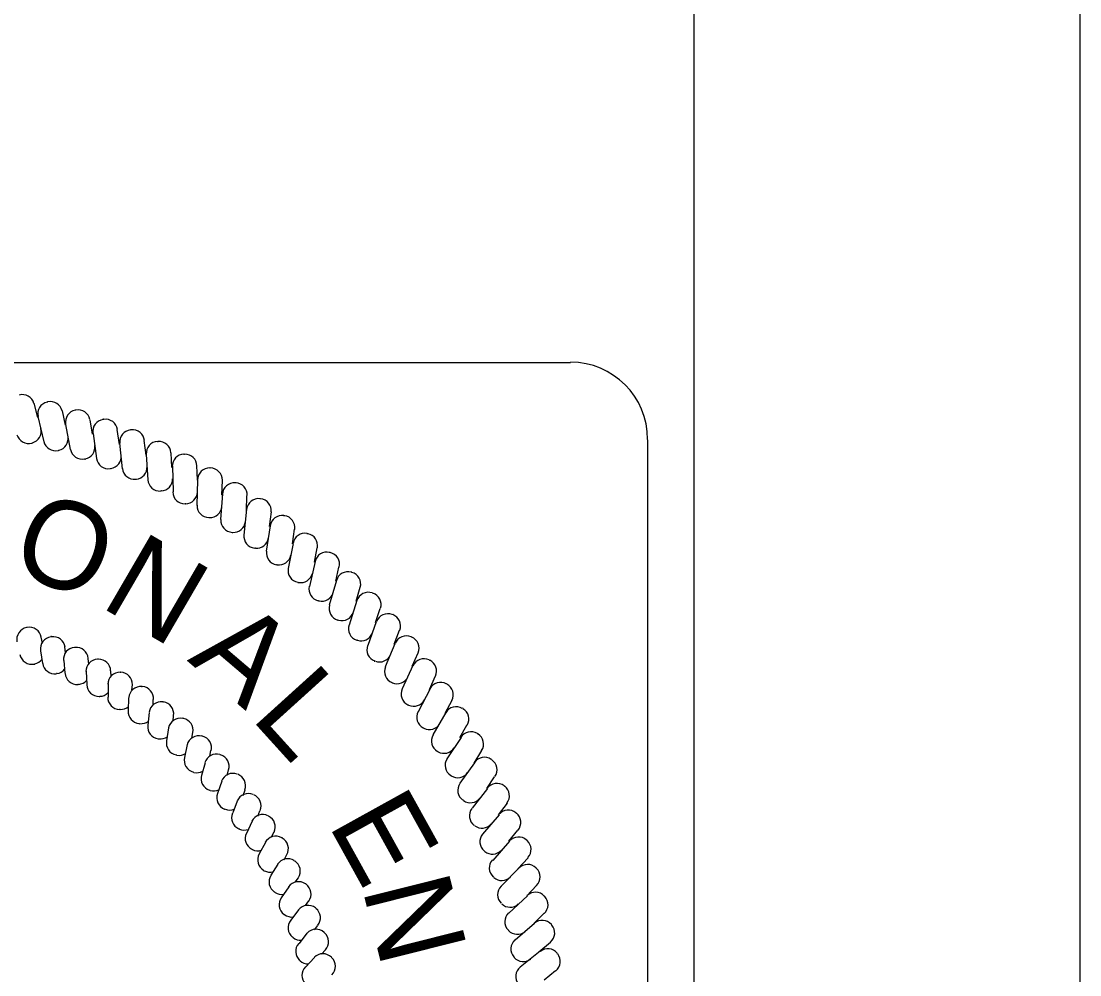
# Model space of a CAD drawing. Extents: x 1458004.1 to 1458040.9, y 194172.7 to 194198.1.
# Drawn here: x 1458038.688 to 1458040.06, y 194177.253 to 194178.489 of the extents above; entities that cross this region are included whole.
import ezdxf

# ---------------------------------------------------------------- set-up
doc = ezdxf.new("R2010")
doc.units = 0
for name, color, linetype in [('Border_9', 7, 'Continuous'), ('Eng_Stamp', 7, 'Continuous'), ('Eng_Stamp_Text_4', 7, 'Continuous'), ('IPlot_Plot_Limits', 7, 'Continuous'), ('Text_Box_4', 7, 'Continuous')]:
    doc.layers.add(name, color=color, linetype=linetype)

msp = doc.modelspace()

# ---------------------------------------------------------------- linework, layer by layer
at = {"layer": 'Border_9'}
msp.add_line((1458039.56, 194194.2392), (1458039.56, 194174.2392), dxfattribs=at)
at = {"layer": 'Eng_Stamp'}
for p, q in [((1458038.71, 194177.9758), (1458038.705, 194177.9942)), ((1458038.7225, 194177.9958), (1458038.7217, 194177.995)), ((1458038.71, 194177.9767), (1458038.7175, 194177.9442)), ((1458038.7458, 194177.9658), (1458038.7417, 194177.9842)), ((1458038.7592, 194177.985), (1458038.7583, 194177.985)), ((1458038.7458, 194177.9667), (1458038.7517, 194177.9342)), ((1458038.7808, 194177.9542), (1458038.7775, 194177.9725)), ((1458038.795, 194177.9733), (1458038.7942, 194177.9733)), ((1458038.7817, 194177.955), (1458038.7858, 194177.9225)), ((1458038.8158, 194177.9408), (1458038.8125, 194177.96)), ((1458038.8308, 194177.96), (1458038.83, 194177.9592)), ((1458038.7017, 194177.9425), (1458038.7025, 194177.9425)), ((1458038.8158, 194177.9425), (1458038.8192, 194177.9092)), ((1458038.85, 194177.9267), (1458038.8475, 194177.9458)), ((1458038.8658, 194177.9442), (1458038.865, 194177.9442)), ((1458038.7367, 194177.9325), (1458038.7375, 194177.9333)), ((1458038.7708, 194177.9217), (1458038.7717, 194177.9217)), ((1458038.85, 194177.9275), (1458038.8525, 194177.895)), ((1458038.8833, 194177.9108), (1458038.8825, 194177.93)), ((1458038.9, 194177.9275), (1458038.8992, 194177.9275)), ((1458038.8042, 194177.9092), (1458038.805, 194177.91)), ((1458038.8842, 194177.9125), (1458038.885, 194177.8792)), ((1458038.9167, 194177.8942), (1458038.9158, 194177.9133)), ((1458038.9333, 194177.91), (1458038.9325, 194177.91)), ((1458038.8367, 194177.8958), (1458038.8375, 194177.8958)), ((1458038.9167, 194177.895), (1458038.9158, 194177.8617)), ((1458038.9483, 194177.875), (1458038.9492, 194177.8942)), ((1458038.8692, 194177.8808), (1458038.87, 194177.8808)), ((1458038.9667, 194177.8908), (1458038.9658, 194177.8908)), ((1458038.9492, 194177.8767), (1458038.9467, 194177.8433)), ((1458038.98, 194177.855), (1458038.9808, 194177.8742)), ((1458038.9983, 194177.87), (1458038.9975, 194177.87)), ((1458038.9008, 194177.8642), (1458038.9017, 194177.8642)), ((1458038.98, 194177.8567), (1458038.9767, 194177.8233)), ((1458039.01, 194177.8342), (1458039.0125, 194177.8533)), ((1458038.9317, 194177.8458), (1458038.9325, 194177.8458)), ((1458039.03, 194177.8483), (1458039.0283, 194177.8483)), ((1458038.9617, 194177.8267), (1458038.9625, 194177.8267)), ((1458039.0108, 194177.835), (1458039.0058, 194177.8025)), ((1458039.04, 194177.8117), (1458039.0425, 194177.8308)), ((1458039.06, 194177.825), (1458039.0583, 194177.825)), ((1458039.0408, 194177.8125), (1458039.0342, 194177.78)), ((1458038.9908, 194177.8067), (1458038.9917, 194177.8067)), ((1458039.0683, 194177.7883), (1458039.0717, 194177.8067)), ((1458039.0883, 194177.8008), (1458039.0875, 194177.8008)), ((1458039.0192, 194177.785), (1458039.02, 194177.785)), ((1458039.0692, 194177.7892), (1458039.0617, 194177.7567)), ((1458039.0958, 194177.7633), (1458039.1, 194177.7817)), ((1458039.1167, 194177.775), (1458039.1158, 194177.775)), ((1458039.0467, 194177.7617), (1458039.0475, 194177.7617)), ((1458039.0967, 194177.7642), (1458039.0875, 194177.7325)), ((1458039.1225, 194177.7375), (1458039.1275, 194177.7558)), ((1458039.1442, 194177.7475), (1458039.1433, 194177.7483)), ((1458039.0733, 194177.7383), (1458039.0742, 194177.7383)), ((1458039.1233, 194177.7383), (1458039.1133, 194177.7067)), ((1458039.1475, 194177.71), (1458039.1533, 194177.7283)), ((1458039.1692, 194177.72), (1458039.1692, 194177.7208)), ((1458038.6958, 194177.7033), (1458038.695, 194177.7033)), ((1458039.0983, 194177.7133), (1458039.0992, 194177.7133)), ((1458039.1483, 194177.7108), (1458039.1375, 194177.68)), ((1458038.7158, 194177.6833), (1458038.7142, 194177.6908)), ((1458038.7275, 194177.6917), (1458038.7267, 194177.6917)), ((1458039.1717, 194177.6817), (1458039.1783, 194177.7)), ((1458039.1942, 194177.6908), (1458039.1933, 194177.6917)), ((1458038.7458, 194177.6708), (1458038.745, 194177.6783)), ((1458038.7583, 194177.6775), (1458038.7575, 194177.6775)), ((1458039.1233, 194177.6875), (1458039.1242, 194177.6867)), ((1458039.1725, 194177.6825), (1458039.16, 194177.6525)), ((1458038.7133, 194177.6733), (1458038.7158, 194177.6567)), ((1458038.7433, 194177.6608), (1458038.745, 194177.6442)), ((1458038.7758, 194177.6558), (1458038.775, 194177.6633)), ((1458038.7883, 194177.6625), (1458038.7875, 194177.6625)), ((1458039.195, 194177.6533), (1458039.2025, 194177.6708)), ((1458039.2175, 194177.6608), (1458039.2167, 194177.6608)), ((1458038.705, 194177.6558), (1458038.7058, 194177.6558)), ((1458038.7725, 194177.6467), (1458038.7733, 194177.6292)), ((1458038.805, 194177.64), (1458038.8042, 194177.6475)), ((1458039.1458, 194177.66), (1458039.1467, 194177.66)), ((1458039.1958, 194177.6542), (1458039.1817, 194177.6242)), ((1458038.7342, 194177.6442), (1458038.735, 194177.6442)), ((1458038.8175, 194177.645), (1458038.8167, 194177.645)), ((1458039.2175, 194177.6233), (1458039.225, 194177.6408)), ((1458038.7617, 194177.63), (1458038.7625, 194177.63)), ((1458038.8008, 194177.6308), (1458038.8008, 194177.6133)), ((1458038.8317, 194177.6225), (1458038.8325, 194177.6292)), ((1458038.845, 194177.6267), (1458038.8442, 194177.6267)), ((1458039.1683, 194177.6325), (1458039.1692, 194177.6317)), ((1458039.2183, 194177.6242), (1458039.2025, 194177.5942)), ((1458039.24, 194177.63), (1458039.2392, 194177.6308)), ((1458038.7892, 194177.6142), (1458038.79, 194177.6142)), ((1458038.8275, 194177.6125), (1458038.8267, 194177.5958)), ((1458038.8592, 194177.6025), (1458038.8592, 194177.61)), ((1458038.8725, 194177.6067), (1458038.8717, 194177.6067)), ((1458039.2375, 194177.5925), (1458039.2467, 194177.6092)), ((1458038.8158, 194177.5975), (1458038.8167, 194177.5975)), ((1458038.8542, 194177.5933), (1458038.8525, 194177.5767)), ((1458039.1892, 194177.6033), (1458039.19, 194177.6033)), ((1458039.2383, 194177.5933), (1458039.2217, 194177.5642)), ((1458039.2608, 194177.5983), (1458039.26, 194177.5992)), ((1458038.8408, 194177.5792), (1458038.8417, 194177.5792)), ((1458038.885, 194177.5825), (1458038.8858, 194177.5892)), ((1458038.8983, 194177.5858), (1458038.8975, 194177.5858)), ((1458038.8792, 194177.5733), (1458038.8767, 194177.5567)), ((1458038.9092, 194177.56), (1458038.9108, 194177.5675)), ((1458039.2092, 194177.5733), (1458039.21, 194177.5733)), ((1458039.2567, 194177.5608), (1458039.2658, 194177.5767)), ((1458039.28, 194177.5658), (1458039.2792, 194177.5658)), ((1458038.8658, 194177.5592), (1458038.8667, 194177.5592)), ((1458038.9033, 194177.5517), (1458038.9, 194177.535)), ((1458038.9233, 194177.5625), (1458038.9225, 194177.5633)), ((1458039.2583, 194177.5608), (1458039.24, 194177.5333)), ((1458038.8892, 194177.5383), (1458038.89, 194177.5383)), ((1458038.9325, 194177.5367), (1458038.9342, 194177.5442)), ((1458038.9467, 194177.5383), (1458038.9458, 194177.5383)), ((1458039.2275, 194177.5433), (1458039.2283, 194177.5425)), ((1458039.275, 194177.5275), (1458039.285, 194177.5442)), ((1458038.9267, 194177.5283), (1458038.9217, 194177.5117)), ((1458039.2758, 194177.5283), (1458039.2567, 194177.5017)), ((1458039.2983, 194177.5325), (1458039.2975, 194177.5325)), ((1458038.9117, 194177.5158), (1458038.9117, 194177.5158)), ((1458038.955, 194177.5117), (1458038.9567, 194177.5192)), ((1458038.9683, 194177.5133), (1458038.9683, 194177.5133)), ((1458039.245, 194177.5117), (1458039.2458, 194177.5117)), ((1458039.2917, 194177.495), (1458039.3017, 194177.51)), ((1458038.9483, 194177.5042), (1458038.9425, 194177.4883)), ((1458039.315, 194177.4975), (1458039.3142, 194177.4983)), ((1458038.9325, 194177.4925), (1458038.9333, 194177.4925)), ((1458038.9758, 194177.4858), (1458038.9783, 194177.4933)), ((1458038.9892, 194177.4867), (1458038.9892, 194177.4867)), ((1458039.2925, 194177.495), (1458039.2725, 194177.4692)), ((1458038.9517, 194177.4683), (1458038.9525, 194177.4675)), ((1458038.9683, 194177.4783), (1458038.9625, 194177.4633)), ((1458039.2608, 194177.48), (1458039.2617, 194177.4792)), ((1458039.3067, 194177.4608), (1458039.3183, 194177.4758)), ((1458038.995, 194177.4592), (1458038.9975, 194177.4658)), ((1458039.0092, 194177.4592), (1458039.0083, 194177.4592)), ((1458039.3075, 194177.4608), (1458039.2858, 194177.4358)), ((1458039.33, 194177.4625), (1458039.3292, 194177.4633)), ((1458038.9708, 194177.4425), (1458038.9717, 194177.4425)), ((1458038.9875, 194177.4525), (1458038.98, 194177.4367)), ((1458039.275, 194177.4475), (1458039.2758, 194177.4467)), ((1458039.0125, 194177.4317), (1458039.0158, 194177.4383)), ((1458039.0267, 194177.4308), (1458039.0258, 194177.4308)), ((1458039.32, 194177.4267), (1458039.3317, 194177.4408)), ((1458039.3442, 194177.4275), (1458039.3433, 194177.4275)), ((1458038.9875, 194177.4158), (1458038.9883, 194177.4158)), ((1458039.005, 194177.425), (1458038.9967, 194177.41)), ((1458039.2883, 194177.4142), (1458039.2892, 194177.4133)), ((1458039.3208, 194177.4267), (1458039.2992, 194177.4017)), ((1458039.0292, 194177.4025), (1458039.0325, 194177.4092)), ((1458039.0425, 194177.4008), (1458039.0417, 194177.4017)), ((1458039.3317, 194177.3908), (1458039.345, 194177.405)), ((1458039.0025, 194177.3883), (1458039.0033, 194177.3883)), ((1458039.0208, 194177.3967), (1458039.0117, 194177.3825)), ((1458039.3333, 194177.3917), (1458039.31, 194177.3683)), ((1458039.3558, 194177.3917), (1458039.355, 194177.3917)), ((1458039.0433, 194177.3733), (1458039.0475, 194177.3792)), ((1458039.3, 194177.3808), (1458039.3008, 194177.38)), ((1458039.0167, 194177.3608), (1458039.0175, 194177.36)), ((1458039.035, 194177.3675), (1458039.025, 194177.3533)), ((1458039.0575, 194177.3708), (1458039.0567, 194177.3717)), ((1458039.3433, 194177.3558), (1458039.3558, 194177.3692)), ((1458039.0567, 194177.3433), (1458039.0608, 194177.3492)), ((1458039.3108, 194177.3458), (1458039.3108, 194177.3458)), ((1458039.3442, 194177.3558), (1458039.32, 194177.3333)), ((1458039.3667, 194177.355), (1458039.3658, 194177.3558)), ((1458039.0292, 194177.3317), (1458039.03, 194177.3317)), ((1458039.0475, 194177.3375), (1458039.0375, 194177.3242)), ((1458039.07, 194177.34), (1458039.0692, 194177.34)), ((1458039.3525, 194177.32), (1458039.3658, 194177.3333)), ((1458039.0683, 194177.3117), (1458039.0725, 194177.3175)), ((1458039.3533, 194177.32), (1458039.3283, 194177.2983)), ((1458039.3758, 194177.3183), (1458039.375, 194177.3183)), ((1458039.0583, 194177.3075), (1458039.0483, 194177.2942)), ((1458039.0817, 194177.3075), (1458039.0808, 194177.3083)), ((1458039.3192, 194177.3117), (1458039.32, 194177.3108)), ((1458039.04, 194177.3025), (1458039.0408, 194177.3017)), ((1458039.3592, 194177.2833), (1458039.3742, 194177.2958)), ((1458039.0775, 194177.28), (1458039.0825, 194177.2858)), ((1458039.3267, 194177.2767), (1458039.3275, 194177.2758)), ((1458039.3608, 194177.2842), (1458039.335, 194177.2633)), ((1458039.3833, 194177.2808), (1458039.3825, 194177.2808)), ((1458039.0492, 194177.2717), (1458039.05, 194177.2717)), ((1458039.0683, 194177.2758), (1458039.0567, 194177.2633)), ((1458039.0908, 194177.2758), (1458039.09, 194177.2758)), ((1458039.3658, 194177.2467), (1458039.3808, 194177.2592))]:
    msp.add_line(p, q, dxfattribs=at)
for centre, start, end in [((1458038.6898, 194177.9897), 15.6, 105.6), ((1458038.7253, 194177.9804), 103.2, 193.2), ((1458038.7261, 194177.9806), 13.2, 103.2), ((1458038.7612, 194177.9697), 100.8, 190.8), ((1458038.762, 194177.9699), 10.8, 100.8), ((1458038.7966, 194177.9576), 98.4, 188.4), ((1458038.7975, 194177.9577), 8.4, 98.4), ((1458038.6978, 194177.9575), 195.6, 285.6), ((1458038.6986, 194177.9578), 285.6, 12.9854), ((1458038.7336, 194177.9483), 283.2, 10.5854), ((1458038.8316, 194177.944), 96, 186), ((1458038.8324, 194177.9441), 6, 96), ((1458038.7328, 194177.9481), 193.2, 283.2), ((1458038.7682, 194177.9373), 280.8, 8.1854), ((1458038.8659, 194177.929), 93.6, 183.6), ((1458038.8667, 194177.929), 3.6, 93.6), ((1458038.7674, 194177.9372), 190.8, 280.8), ((1458038.8014, 194177.9248), 188.4, 278.4), ((1458038.8023, 194177.925), 278.4, 5.7854), ((1458038.8995, 194177.9125), 91.2, 181.2), ((1458038.9004, 194177.9125), 1.2, 91.2), ((1458038.835, 194177.9111), 186, 276), ((1458038.8358, 194177.9111), 276, 3.3854), ((1458038.9324, 194177.8946), 88.8, 178.8), ((1458038.9333, 194177.8946), 358.8, 88.8), ((1458038.8679, 194177.8959), 183.6, 273.6), ((1458038.8688, 194177.896), 273.6, 0.9854), ((1458038.9646, 194177.8754), 86.4, 176.4), ((1458038.9655, 194177.8754), 356.4, 86.4), ((1458038.9002, 194177.8794), 181.2, 271.2), ((1458038.901, 194177.8794), 271.2, 358.5854), ((1458038.9959, 194177.8549), 84, 174), ((1458038.9968, 194177.8548), 354, 84), ((1458038.9317, 194177.8615), 178.8, 268.8), ((1458038.9326, 194177.8615), 268.8, 356.1854), ((1458038.9625, 194177.8423), 176.4, 266.4), ((1458038.9633, 194177.8423), 266.4, 353.7854), ((1458039.0264, 194177.833), 81.6, 171.6), ((1458039.0272, 194177.8329), 351.6, 81.6), ((1458039.0558, 194177.8099), 79.2, 169.2), ((1458039.0567, 194177.8097), 349.2, 79.2), ((1458038.9924, 194177.8219), 174, 264), ((1458038.9933, 194177.8218), 264, 351.3854), ((1458039.0215, 194177.8002), 171.6, 261.6), ((1458039.0843, 194177.7856), 76.8, 166.8), ((1458039.0852, 194177.7854), 346.8, 76.8), ((1458039.0223, 194177.8001), 261.6, 348.9854), ((1458039.0496, 194177.7774), 169.2, 259.2), ((1458039.0504, 194177.7772), 259.2, 346.5854), ((1458039.1118, 194177.7601), 74.4, 164.4), ((1458039.1126, 194177.7599), 344.4, 74.4), ((1458039.0767, 194177.7533), 166.8, 256.8), ((1458039.0776, 194177.7531), 256.8, 344.1854), ((1458039.1382, 194177.7335), 72, 162), ((1458039.139, 194177.7332), 342, 72), ((1458039.1028, 194177.7282), 164.4, 254.4), ((1458039.1037, 194177.7279), 254.4, 341.7854), ((1458039.1634, 194177.7058), 69.6, 159.6), ((1458039.1642, 194177.7055), 339.6, 69.6), ((1458038.6981, 194177.688), 100.8287, 190.8287), ((1458038.699, 194177.6881), 10.8287, 100.8287), ((1458039.1279, 194177.702), 162, 252), ((1458038.7287, 194177.6758), 97.7253, 187.7253), ((1458038.7296, 194177.676), 7.7253, 97.7253), ((1458039.1287, 194177.7017), 252, 339.3854), ((1458039.1874, 194177.677), 67.2, 157.2), ((1458039.1882, 194177.6767), 337.2, 67.2), ((1458038.7586, 194177.6621), 94.6219, 184.6219), ((1458038.7595, 194177.6622), 4.6219, 94.6219), ((1458039.1518, 194177.6747), 159.6, 249.6), ((1458038.702, 194177.6714), 190.8287, 280.8287), ((1458038.7028, 194177.6716), 280.8287, 323.8608), ((1458038.7877, 194177.6467), 91.5185, 181.5185), ((1458038.7886, 194177.6468), 1.5185, 91.5185), ((1458039.1526, 194177.6744), 249.6, 336.9854), ((1458039.2102, 194177.6473), 64.8, 154.8), ((1458039.211, 194177.6469), 334.8, 64.8), ((1458038.7316, 194177.6591), 187.7253, 277.7253), ((1458038.7325, 194177.6593), 277.7253, 320.7574), ((1458039.1746, 194177.6465), 157.2, 247.2), ((1458038.7606, 194177.6453), 184.6219, 274.6219), ((1458038.7615, 194177.6453), 274.6219, 317.654), ((1458038.816, 194177.6298), 88.4151, 178.4151), ((1458038.8168, 194177.6298), 358.4151, 88.4151), ((1458039.1753, 194177.6462), 247.2, 334.5854), ((1458038.7888, 194177.6298), 181.5185, 271.5185), ((1458038.8432, 194177.6114), 85.3117, 175.3117), ((1458038.8441, 194177.6114), 355.3117, 85.3117), ((1458039.1961, 194177.6174), 154.8, 244.8), ((1458039.2318, 194177.6167), 62.4, 152.4), ((1458039.2326, 194177.6163), 332.4, 62.4), ((1458038.7897, 194177.6299), 271.5185, 314.5506), ((1458038.8161, 194177.6129), 178.4151, 268.4151), ((1458038.8695, 194177.5916), 82.2083, 172.2083), ((1458038.8703, 194177.5915), 352.2083, 82.2083), ((1458039.1969, 194177.617), 244.8, 332.1854), ((1458038.817, 194177.6129), 268.4151, 311.4472), ((1458038.8425, 194177.5945), 175.3117, 265.3117), ((1458039.2164, 194177.5873), 152.4, 242.4), ((1458039.252, 194177.5852), 60, 150), ((1458039.2528, 194177.5847), 330, 60), ((1458038.8434, 194177.5944), 265.3117, 308.3438), ((1458038.8946, 194177.5703), 79.1049, 169.1049), ((1458038.8955, 194177.5702), 349.1049, 79.1049), ((1458039.2172, 194177.5869), 242.4, 329.7854), ((1458038.8678, 194177.5747), 172.2083, 262.2083), ((1458039.271, 194177.5528), 57.6, 147.6), ((1458039.2717, 194177.5524), 327.6, 57.6), ((1458038.8687, 194177.5746), 262.2083, 305.2404), ((1458038.892, 194177.5536), 169.1049, 259.1049), ((1458038.9185, 194177.5477), 76.0015, 166.0015), ((1458038.9194, 194177.5475), 346.0015, 76.0015), ((1458039.2354, 194177.5565), 150, 240), ((1458038.8929, 194177.5534), 259.1049, 302.137), ((1458038.9412, 194177.5239), 72.8981, 162.8981), ((1458038.9421, 194177.5236), 342.8981, 72.8981), ((1458039.2362, 194177.556), 240, 327.3854), ((1458038.9151, 194177.5312), 166.0015, 256.0015), ((1458039.2532, 194177.5249), 147.6, 237.6), ((1458039.2885, 194177.5197), 55.2, 145.2), ((1458039.2892, 194177.5192), 325.2, 55.2), ((1458038.9159, 194177.5309), 256.0015, 299.0336), ((1458038.9369, 194177.5075), 162.8981, 252.8981), ((1458038.9626, 194177.4989), 69.7947, 159.7947), ((1458038.9634, 194177.4986), 339.7947, 69.7947), ((1458039.2539, 194177.5244), 237.6, 324.9854), ((1458039.2696, 194177.4925), 145.2, 235.2), ((1458039.3046, 194177.4859), 52.8, 142.8), ((1458039.3053, 194177.4854), 322.8, 52.8), ((1458038.9377, 194177.5073), 252.8981, 295.9302), ((1458038.9573, 194177.4828), 159.7947, 249.7947), ((1458038.9826, 194177.4727), 66.6913, 156.6913), ((1458038.9834, 194177.4724), 336.6913, 66.6913), ((1458039.2703, 194177.492), 235.2, 322.5854), ((1458039.2846, 194177.4595), 142.8, 232.8), ((1458038.9582, 194177.4825), 249.7947, 292.8268), ((1458038.9765, 194177.4569), 156.6913, 246.6913), ((1458039.0011, 194177.4455), 63.5879, 153.5879), ((1458039.0019, 194177.4451), 333.5879, 63.5879), ((1458039.3194, 194177.4514), 50.4, 140.4), ((1458039.32, 194177.4509), 320.4, 50.4), ((1458038.9773, 194177.4566), 246.6913, 289.7234), ((1458039.2853, 194177.459), 232.8, 320.1854), ((1458038.9941, 194177.4301), 153.5879, 243.5879), ((1458039.0181, 194177.4174), 60.4845, 150.4845), ((1458039.0189, 194177.4169), 330.4845, 60.4845), ((1458039.2982, 194177.4259), 140.4, 230.4), ((1458039.3326, 194177.4164), 48, 138), ((1458039.3333, 194177.4158), 318, 48), ((1458038.9949, 194177.4297), 243.5879, 286.62), ((1458039.2989, 194177.4254), 230.4, 317.7854), ((1458039.0103, 194177.4023), 150.4845, 240.4845), ((1458039.0336, 194177.3883), 57.3811, 147.3811), ((1458039.0343, 194177.3879), 327.3811, 57.3811), ((1458039.3104, 194177.3918), 138, 228), ((1458039.0111, 194177.4019), 240.4845, 283.5166), ((1458039.3444, 194177.3808), 45.6, 135.6), ((1458039.345, 194177.3802), 315.6, 45.6), ((1458039.025, 194177.3737), 147.3811, 237.3811), ((1458039.0475, 194177.3585), 54.2777, 144.2777), ((1458039.3111, 194177.3912), 228, 315.3854), ((1458039.0257, 194177.3732), 237.3811, 280.4132), ((1458039.0482, 194177.358), 324.2777, 54.2777), ((1458039.3212, 194177.3572), 135.6, 225.6), ((1458039.3547, 194177.3448), 43.2, 133.2), ((1458039.0381, 194177.3444), 144.2777, 234.2777), ((1458039.3218, 194177.3566), 225.6, 312.9854), ((1458039.3553, 194177.3442), 313.2, 43.2), ((1458039.0388, 194177.3439), 234.2777, 277.3098), ((1458039.0597, 194177.3279), 51.1743, 141.1743), ((1458039.0604, 194177.3274), 321.1743, 51.1743), ((1458039.3305, 194177.3222), 133.2, 223.2), ((1458039.0496, 194177.3143), 141.1743, 231.1743), ((1458039.3634, 194177.3084), 40.8, 130.8), ((1458039.364, 194177.3077), 310.8, 40.8), ((1458039.0703, 194177.2968), 48.0709, 138.0709), ((1458039.0709, 194177.2962), 318.0709, 48.0709), ((1458039.3311, 194177.3215), 223.2, 310.5854), ((1458039.0503, 194177.3138), 231.1743, 274.2064), ((1458039.0595, 194177.2837), 138.0709, 228.0709), ((1458039.3383, 194177.2868), 130.8, 220.8), ((1458039.0792, 194177.2651), 44.9675, 134.9675), ((1458039.3707, 194177.2716), 38.4, 128.4), ((1458039.3712, 194177.2709), 308.4, 38.4), ((1458039.0601, 194177.2832), 228.0709, 271.103), ((1458039.0676, 194177.2527), 134.9675, 224.9675), ((1458039.0798, 194177.2645), 314.9675, 44.9675), ((1458039.3389, 194177.2861), 220.8, 308.1854), ((1458039.3447, 194177.2511), 128.4, 218.4)]:
    msp.add_arc(centre, 0.0156, start, end, dxfattribs=at)
at = {"layer": 'IPlot_Plot_Limits'}
msp.add_line((1458040.06, 194195.7392), (1458040.06, 194172.7392), dxfattribs=at)
at = {"layer": 'Text_Box_4'}
for p, q in [((1458032.0967, 194178.0467), (1458039.4, 194178.0467)), ((1458039.5, 194177.9467), (1458039.5, 194176.2075))]:
    msp.add_line(p, q, dxfattribs=at)
msp.add_arc((1458039.4, 194177.9473), 0.1, 0, 90, dxfattribs=at)

# ---------------------------------------------------------------- texts
at = {"layer": 'Eng_Stamp_Text_4'}
for s, rotation, p in [('O', 338.9971, (1458038.67, 194177.7783)), ('N', 329.8047, (1458038.7883, 194177.7317)), ('A', 319.5582, (1458038.9025, 194177.6608)), ('L', 312.1609, (1458038.9842, 194177.5867)), ('E', 298.9789, (1458039.085, 194177.4492)), ('N', 284.0912, (1458039.13, 194177.3658))]:
    msp.add_text(s, height=0.1137, rotation=rotation, dxfattribs=at).set_placement(p)

doc.saveas('drawing.dxf')
